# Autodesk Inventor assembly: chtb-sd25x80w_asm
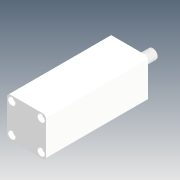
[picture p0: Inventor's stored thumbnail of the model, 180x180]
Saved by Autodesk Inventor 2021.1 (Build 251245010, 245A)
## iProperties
Company: Microsoft
Created: 2018-05
Part Number: chtb-sd25x80w_asm
Description: STEP AP214
Document SubType Name: Assembly
Designer: user
Title: chtb-sd25x80w_asm.STEP
Author: Windows
Revision Number: ÈÎºÎ
Sending System: SolidWorks 2015
Preprocessor: SwSTEP 2.0
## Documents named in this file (4)
- D:\Vault_2016\Projekty\Clamptek\Hydraulic\CHTB\CHTB-25\Inventor\chtb-sd25x80w\chtb-sd25x80w_asm.iam
- D:\Vault_2016\Projekty\Clamptek\Hydraulic\CHTB\CHTB-25\Inventor\chtb-sd25x80w\CHTB-25QG.ipt
- D:\Vault_2016\Projekty\Clamptek\Hydraulic\CHTB\CHTB-25\Inventor\chtb-sd25x80w\CHTB-SD25X80NBT.ipt
- D:\Vault_2016\Projekty\Clamptek\Hydraulic\CHTB\CHTB-25\Inventor\chtb-sd25x80w\CHTB-SD25X80WHSG.ipt
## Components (3 placed, 3 different names)
1. CHTB-25QG_1
2. CHTB-SD25X80NBT_2
3. CHTB-SD25X80WHSG_3
